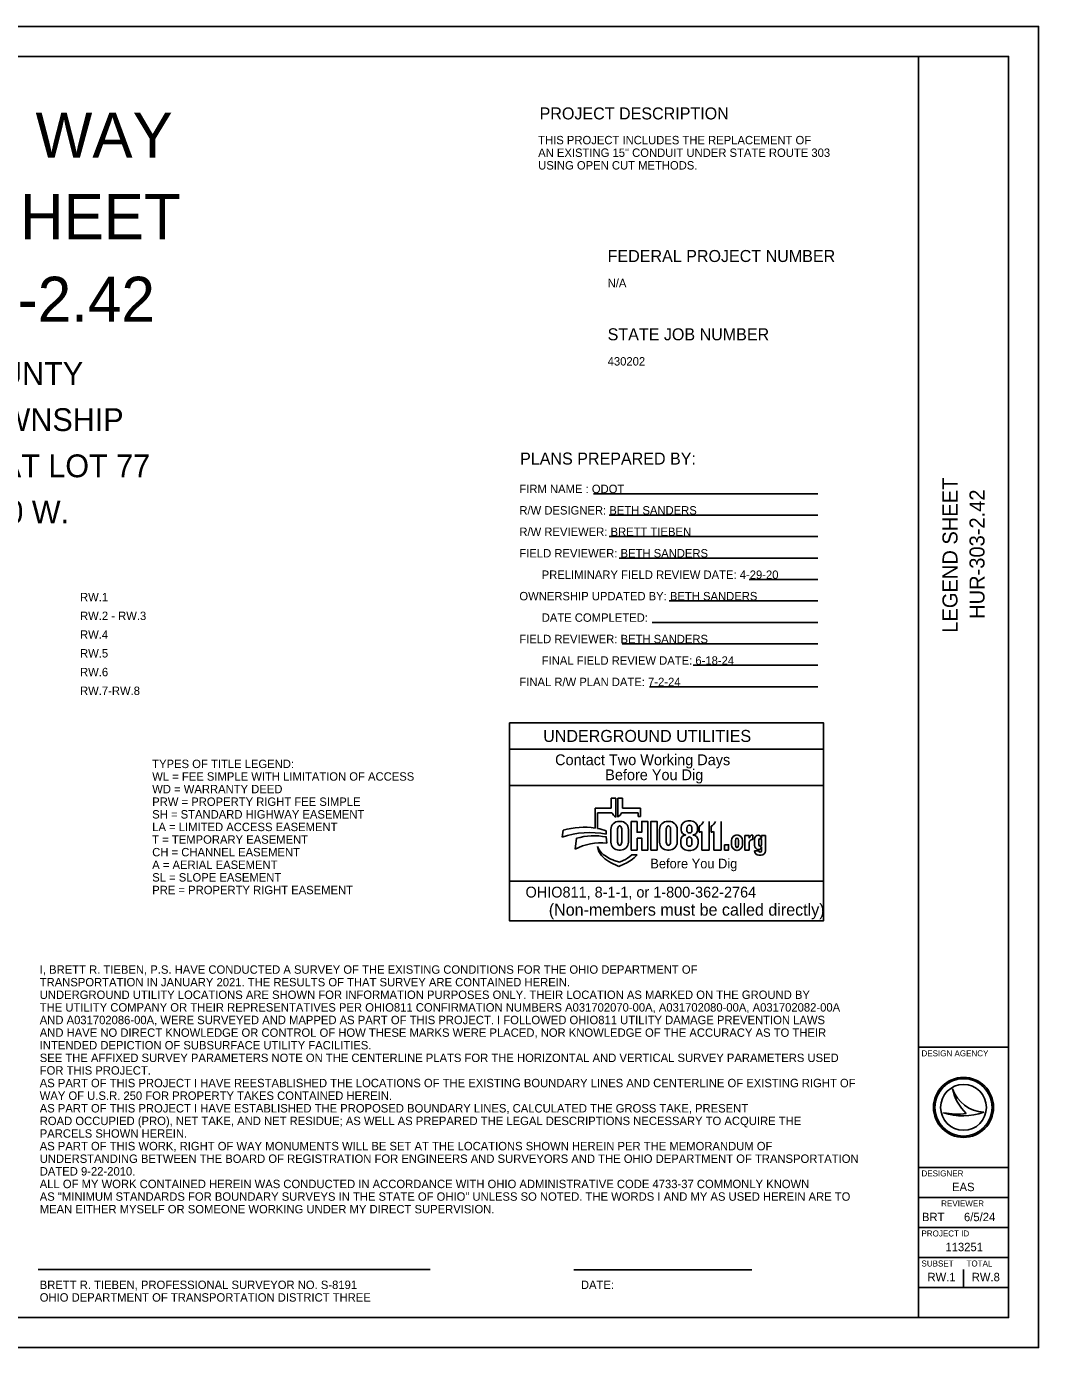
# Model space of a CAD drawing. Extents: x 0 to 34, y 0 to 22.
# Drawn here: x 17.15 to 34, y 0 to 22 of the extents above; entities that cross this region are included whole.
import ezdxf

# ---------------------------------------------------------------- set-up
doc = ezdxf.new("R2010")
doc.units = 0
for name, color, linetype in [('Default', 7, 'Continuous'), ('SH_Border', 7, 'Continuous'), ('SH_Cut_Line', 7, 'Continuous'), ('SH_Data', 7, 'Continuous'), ('SH_Text', 7, 'Continuous')]:
    doc.layers.add(name, color=color, linetype=linetype)

msp = doc.modelspace()

# ---------------------------------------------------------------- linework, layer by layer
at = {"layer": 'Default'}
for p, q in [((17.342, 1.298), (23.871, 1.298)), ((26.261, 1.297), (29.226, 1.297))]:
    msp.add_line(p, q, dxfattribs=at)
at = {"layer": 'SH_Border'}
for p, q in [((32, 0.5), (32, 21.5)), ((32, 5), (33.5, 5)), ((32, 3), (33.5, 3)), ((32, 2.5), (33.5, 2.5)), ((32, 2), (33.5, 2)), ((32, 1.5), (33.5, 1.5)), ((32, 1), (33.5, 1))]:
    msp.add_line(p, q, dxfattribs=at)
msp.add_lwpolyline([(1.5, 21.5), (33.5, 21.5), (33.5, 0.5), (1.5, 0.5)], close=True, dxfattribs=at)
at = {"layer": 'SH_Cut_Line'}
msp.add_lwpolyline([(0, 0), (34, 0), (34, 22), (0, 22)], close=True, dxfattribs=at)
at = {"layer": 'SH_Data'}
for p, q in [((26.961, 9.151), (26.881, 9.151)), ((26.881, 9.151), (26.881, 8.984)), ((26.961, 8.834), (26.961, 9.151)), ((27.072, 9.151), (26.992, 9.151)), ((26.992, 9.151), (26.992, 8.834)), ((27.072, 8.984), (27.072, 9.151)), ((26.881, 8.984), (26.618, 8.984)), ((26.618, 8.984), (26.618, 8.65)), ((26.655, 8.643), (26.655, 8.907)), ((26.655, 8.907), (26.896, 8.907)), ((27.056, 8.907), (27.335, 8.907)), ((27.369, 8.984), (27.072, 8.984)), ((27.335, 8.907), (27.335, 8.844)), ((27.335, 8.844), (27.369, 8.844)), ((27.369, 8.844), (27.369, 8.984)), ((26.083, 8.615), (26.069, 8.499)), ((26.802, 8.548), (26.802, 8.606)), ((26.879, 8.629), (26.879, 8.417)), ((26.988, 8.434), (26.988, 8.617)), ((27.037, 8.763), (27.013, 8.763)), ((27.062, 8.617), (27.062, 8.434)), ((27.171, 8.417), (27.171, 8.629)), ((27.315, 8.761), (27.214, 8.761)), ((27.214, 8.761), (27.214, 8.283)), ((27.69, 8.629), (27.69, 8.417)), ((27.799, 8.434), (27.799, 8.617)), ((27.848, 8.763), (27.823, 8.763)), ((27.873, 8.617), (27.873, 8.434)), ((27.982, 8.417), (27.982, 8.629)), ((28.046, 8.655), (28.046, 8.619)), ((28.145, 8.602), (28.145, 8.661)), ((28.209, 8.769), (28.16, 8.769)), ((28.226, 8.661), (28.226, 8.602)), ((28.323, 8.619), (28.323, 8.655)), ((28.346, 8.581), (28.346, 8.683)), ((28.394, 8.283), (28.394, 8.595)), ((28.513, 8.761), (28.513, 8.283)), ((28.546, 8.581), (28.546, 8.683)), ((28.595, 8.283), (28.595, 8.595)), ((28.713, 8.761), (28.713, 8.283)), ((26.303, 8.48), (26.281, 8.301)), ((26.812, 8.397), (26.802, 8.503)), ((27.315, 8.283), (27.315, 8.485)), ((28.041, 8.449), (28.041, 8.398)), ((28.142, 8.389), (28.142, 8.45)), ((28.227, 8.45), (28.227, 8.389)), ((28.329, 8.398), (28.329, 8.449)), ((28.887, 8.374), (28.887, 8.442)), ((28.954, 8.373), (28.954, 8.442)), ((29.002, 8.442), (29.002, 8.373)), ((29.069, 8.442), (29.069, 8.374)), ((29.182, 8.527), (29.109, 8.527)), ((29.109, 8.527), (29.109, 8.283)), ((29.182, 8.48), (29.182, 8.527)), ((29.182, 8.283), (29.182, 8.411)), ((29.231, 8.46), (29.242, 8.46)), ((29.242, 8.535), (29.237, 8.535)), ((29.242, 8.46), (29.242, 8.535)), ((29.271, 8.362), (29.271, 8.466)), ((29.343, 8.376), (29.343, 8.452)), ((29.386, 8.482), (29.386, 8.528)), ((29.386, 8.528), (29.451, 8.528)), ((29.386, 8.452), (29.386, 8.376)), ((29.451, 8.528), (29.451, 8.27)), ((26.654, 8.343), (26.659, 8.317)), ((27.013, 8.283), (27.037, 8.283)), ((27.214, 8.283), (27.315, 8.283)), ((27.313, 8.203), (27.227, 8.203)), ((27.31, 8.201), (27.313, 8.203)), ((27.823, 8.283), (27.848, 8.283)), ((28.162, 8.277), (28.208, 8.277)), ((28.513, 8.283), (28.394, 8.283)), ((28.713, 8.283), (28.595, 8.283)), ((29.109, 8.283), (29.182, 8.283)), ((29.271, 8.27), (29.343, 8.27)), ((29.381, 8.2), (29.341, 8.2)), ((29.386, 8.27), (29.386, 8.339)), ((27.019, 8.083), (26.931, 8.113)), ((26.955, 8.037), (27.01, 8.012)), ((27.01, 8.012), (27.105, 8.053)), ((27.081, 8.109), (27.019, 8.083)), ((30.417, 7.105), (25.192, 7.105)), ((32.567, 4.31), (32.567, 4.31)), ((32.75, 4), (32.75, 4)), ((32.417, 3.91), (32.417, 3.91)), ((33.087, 3.919), (33.087, 3.919)), ((32.75, 1), (32.75, 1.3))]:
    msp.add_line(p, q, dxfattribs=at)
for points in [[(25.192, 10.405), (30.417, 10.405), (30.417, 9.965), (25.192, 9.965)], [(25.192, 9.965), (30.417, 9.965), (30.417, 9.36), (25.192, 9.36)], [(25.192, 9.36), (30.417, 9.36), (30.417, 7.765), (25.192, 7.765)], [(28.771, 8.373), (28.837, 8.373), (28.837, 8.283), (28.771, 8.283)], [(25.192, 7.765), (30.417, 7.765), (30.417, 7.105), (25.192, 7.105)]]:
    msp.add_lwpolyline(points, close=True, dxfattribs=at)
for points in [[(27.315, 8.485), (27.391, 8.485), (27.391, 8.283), (27.493, 8.283), (27.493, 8.761), (27.391, 8.761), (27.391, 8.581), (27.315, 8.581), (27.315, 8.761)], [(27.544, 8.283), (27.646, 8.283), (27.646, 8.761), (27.544, 8.761), (27.544, 8.283)], [(28.127, 8.535), (28.127, 8.535)], [(28.243, 8.535), (28.243, 8.535)]]:
    msp.add_lwpolyline(points, dxfattribs=at)
for radius in [0.5, 0.477, 0.477, 0.382]:
    msp.add_circle((32.75, 4), radius, dxfattribs=at)
for centre, radius, start, end in [((27.033, 8.962), 0.147, 201.9296, 240.7469), ((26.92, 8.962), 0.147, 299.2531, 338.0704), ((26.426, 7.441), 1.224, 81.0007, 106.3144), ((26.426, 7.441), 1.224, 72.1402, 79.2074), ((27.013, 8.629), 0.134, 90, 180), ((27.037, 8.629), 0.134, 0, 90), ((27.823, 8.629), 0.134, 90, 180), ((27.848, 8.629), 0.134, 0, 90), ((28.16, 8.655), 0.114, 90, 180), ((28.13, 8.619), 0.0837, 180, 268.1442), ((28.209, 8.655), 0.114, 0, 90), ((28.24, 8.619), 0.0837, 272.2058, 0), ((28.296, 8.805), 0.132, 292.5572, 340.7355), ((28.334, 8.713), 0.132, 275.1733, 297.0931), ((28.496, 8.805), 0.132, 292.5572, 340.7355), ((28.534, 8.713), 0.132, 275.1733, 297.0931), ((26.52, 7.245), 1.332, 77.8238, 109.8274), ((26.709, 7.453), 0.95, 83.8248, 116.8021), ((26.602, 7.428), 1.094, 79.44, 105.8467), ((27.013, 8.417), 0.134, 180, 270), ((27.037, 8.417), 0.134, 270, 0), ((27.823, 8.417), 0.134, 180, 270), ((27.848, 8.417), 0.134, 270, 0), ((28.127, 8.449), 0.0865, 90, 180), ((28.162, 8.398), 0.121, 180, 270), ((28.208, 8.398), 0.121, 270, 0), ((28.243, 8.449), 0.0865, 0, 90), ((28.982, 8.442), 0.0956, 92.5886, 180), ((28.982, 8.374), 0.0956, 180, 267.4114), ((28.974, 8.442), 0.0956, 0, 87.4114), ((28.974, 8.374), 0.0956, 272.5886, 0), ((29.237, 8.48), 0.0548, 90, 180), ((29.231, 8.411), 0.0493, 90, 180), ((29.339, 8.466), 0.0686, 92.6865, 180), ((29.34, 8.362), 0.0692, 180, 265.7132), ((29.333, 8.482), 0.0524, 0, 86.9262), ((26.934, 8.451), 0.3, 201.0457, 232.5314), ((26.87, 8.353), 0.214, 189.6817, 216.0884), ((27.07, 8.498), 0.461, 216.0884, 235.7167), ((27.222, 8.826), 0.773, 232.5314, 241.794), ((27.095, 8.589), 0.504, 241.794, 250.9821), ((26.866, 8.603), 0.538, 293.4582, 312.0712), ((26.866, 8.603), 0.599, 293.4582, 317.8286), ((29.341, 8.27), 0.0699, 180, 270), ((29.339, 8.339), 0.0467, 264.7825, 0), ((29.381, 8.27), 0.0699, 270, 0), ((27.318, 8.863), 0.903, 235.7167, 246.2325), ((33.116, 4.498), 0.58, 198.9257, 198.9319), ((33.347, 4.47), 0.796, 191.6379, 191.6421), ((33.116, 4.498), 0.58, 198.9319, 267.1657), ((33.347, 4.47), 0.796, 191.6421, 226.0947), ((32.739, 4.87), 1.013, 251.4576, 290.0832), ((32.648, 5.154), 1.266, 259.4964, 259.4995), ((32.739, 4.87), 1.013, 251.4527, 251.4576), ((32.648, 5.154), 1.266, 259.4995, 276.6672)]:
    msp.add_arc(centre, radius, start, end, dxfattribs=at)
for centre, major_axis, ratio, start_param, end_param in [((27.025, 8.617), (0, 0.0723), 0.514403, 4.712389, 7.853982), ((27.836, 8.617), (0, 0.0723), 0.514403, 4.712389, 7.853982), ((28.186, 8.661), (0.0404, 0), 0.969373, 0, 3.141593), ((28.186, 8.602), (0.0404, 0), 0.818453, 3.141593, 6.283185), ((27.025, 8.434), (0, 0.0723), 0.514403, 1.570796, 4.712389), ((27.836, 8.434), (0, 0.0723), 0.514403, 1.570796, 4.712389), ((28.184, 8.45), (0, 0.0535), 0.794529, 4.712389, 7.853982), ((28.184, 8.389), (0.0425, 0), 0.959837, 3.141593, 6.283185), ((28.978, 8.442), (0, 0.0434), 0.553236, 4.712389, 7.853982), ((28.978, 8.373), (0, 0.046), 0.522014, 1.570796, 4.712389), ((29.364, 8.452), (0, 0.0275), 0.777179, 4.712389, 7.853982), ((29.364, 8.376), (0, 0.0275), 0.777179, 1.570796, 4.712389), ((29.364, 8.27), (0.0214, 0), 0.959012, 3.141593, 6.283185)]:
    msp.add_ellipse(centre, major_axis=major_axis, ratio=ratio, start_param=start_param, end_param=end_param, dxfattribs=at)
at = {"layer": 'SH_Text'}
for p, q in [((26.586, 14.219), (30.323, 14.219)), ((26.85, 13.862), (30.323, 13.862)), ((26.85, 13.505), (30.323, 13.505)), ((27.014, 13.148), (30.323, 13.148)), ((29.178, 12.79), (30.323, 12.79)), ((27.85, 12.433), (30.323, 12.433)), ((27.565, 12.076), (30.323, 12.076)), ((27.068, 11.719), (30.323, 11.719)), ((28.249, 11.362), (30.323, 11.362)), ((27.52, 11.005), (30.323, 11.005))]:
    msp.add_line(p, q, dxfattribs=at)

# ---------------------------------------------------------------- texts
at = {"layer": 'Default'}
for s, p in [('I, BRETT R. TIEBEN, P.S. HAVE CONDUCTED A SURVEY OF THE EXISTING CONDITIONS FOR THE OHIO DEPARTMENT OF', (17.367, 6.225)), ('TRANSPORTATION IN JANUARY 2021. THE RESULTS OF THAT SURVEY ARE CONTAINED HEREIN.', (17.367, 6.015)), ('UNDERGROUND UTILITY LOCATIONS ARE SHOWN FOR INFORMATION PURPOSES ONLY. THEIR LOCATION AS MARKED ON THE GROUND BY ', (17.367, 5.805)), ('THE UTILITY COMPANY OR THEIR REPRESENTATIVES PER OHIO811 CONFIRMATION NUMBERS A031702070-00A, A031702080-00A, A031702082-00A', (17.367, 5.595)), ('AND A031702086-00A, WERE SURVEYED AND MAPPED AS PART OF THIS PROJECT. I FOLLOWED OHIO811 UTILITY DAMAGE PREVENTION LAWS', (17.367, 5.385)), ('AND HAVE NO DIRECT KNOWLEDGE OR CONTROL OF HOW THESE MARKS WERE PLACED, NOR KNOWLEDGE OF THE ACCURACY AS TO THEIR', (17.367, 5.175)), ('INTENDED DEPICTION OF SUBSURFACE UTILITY FACILITIES.', (17.367, 4.965)), ('SEE THE AFFIXED SURVEY PARAMETERS NOTE ON THE CENTERLINE PLATS FOR THE HORIZONTAL AND VERTICAL SURVEY PARAMETERS USED ', (17.367, 4.755)), ('FOR THIS PROJECT.', (17.367, 4.545)), ('AS PART OF THIS PROJECT I HAVE REESTABLISHED THE LOCATIONS OF THE EXISTING BOUNDARY LINES AND CENTERLINE OF EXISTING RIGHT OF ', (17.367, 4.335)), ('WAY OF U.S.R. 250 FOR PROPERTY TAKES CONTAINED HEREIN.', (17.367, 4.125)), ('AS PART OF THIS PROJECT I HAVE ESTABLISHED THE PROPOSED BOUNDARY LINES, CALCULATED THE GROSS TAKE, PRESENT', (17.367, 3.915)), ('ROAD OCCUPIED (PRO), NET TAKE, AND NET RESIDUE; AS WELL AS PREPARED THE LEGAL DESCRIPTIONS NECESSARY TO ACQUIRE THE', (17.367, 3.705)), ('PARCELS SHOWN HEREIN.', (17.367, 3.495)), ('AS PART OF THIS WORK, RIGHT OF WAY MONUMENTS WILL BE SET AT THE LOCATIONS SHOWN HEREIN PER THE MEMORANDUM OF ', (17.367, 3.285)), ('UNDERSTANDING BETWEEN THE BOARD OF REGISTRATION FOR ENGINEERS AND SURVEYORS AND THE OHIO DEPARTMENT OF TRANSPORTATION ', (17.367, 3.075)), ('DATED 9-22-2010.', (17.367, 2.865)), ('ALL OF MY WORK CONTAINED HEREIN WAS CONDUCTED IN ACCORDANCE WITH OHIO ADMINISTRATIVE CODE 4733-37 COMMONLY KNOWN', (17.367, 2.655)), ('AS "MINIMUM STANDARDS FOR BOUNDARY SURVEYS IN THE STATE OF OHIO" UNLESS SO NOTED. THE WORDS I AND MY AS USED HEREIN ARE TO', (17.367, 2.445)), ('MEAN EITHER MYSELF OR SOMEONE WORKING UNDER MY DIRECT SUPERVISION.', (17.367, 2.235)), ('BRETT R. TIEBEN, PROFESSIONAL SURVEYOR NO. S-8191                                                               ', (17.367, 0.975)), (' DATE:', (26.327, 0.975)), ('OHIO DEPARTMENT OF TRANSPORTATION DISTRICT THREE', (17.367, 0.765))]:
    msp.add_text(s, height=0.14, dxfattribs=at).set_placement(p)
at = {"layer": 'SH_Data'}
for s, height, p in [('RIGHT OF WAY', 0.75, (12.227, 19.816)), ('LEGEND SHEET', 0.75, (11.968, 18.457)), (' HUR-303-2.42', 0.75, (12.541, 17.082)), ('      HURON COUNTY     ', 0.38, (13.093, 16.03)), ('    WAKEMAN TOWNSHIP   ', 0.38, (12.694, 15.262)), ('SECTION 1, GREAT LOT 77', 0.38, (12.654, 14.493)), ('   T. 4 N., R. 20 W.   ', 0.38, (13.649, 13.725)), ('RW.1  ', 0.14, (18.038, 12.427)), ('RW.2 - RW.3 ', 0.14, (18.038, 12.115)), ('RW.4  ', 0.14, (18.038, 11.803)), ('RW.5  ', 0.14, (18.038, 11.491)), ('RW.6  ', 0.14, (18.038, 11.179)), ('RW.7-RW.8 ', 0.14, (18.038, 10.867)), ('UNDERGROUND UTILITIES', 0.2, (25.751, 10.085)), ('Contact Two Working Days', 0.18, (25.949, 9.698)), ('Before You Dig', 0.18, (26.784, 9.448)), ('Before You Dig', 0.15972, (27.535, 7.98)), ('OHIO811, 8-1-1, or 1-800-362-2764', 0.18, (25.457, 7.494)), ('(Non-members must be called directly)', 0.2, (25.844, 7.192)), ('DESIGN AGENCY', 0.1, (32.05, 4.85)), ('DESIGNER', 0.1, (32.05, 2.85)), ('EAS', 0.14, (32.559, 2.605)), ('REVIEWER', 0.1, (32.378, 2.35)), ('BRT', 0.14, (32.058, 2.105)), ('6/5/24', 0.14, (32.758, 2.105)), ('PROJECT ID', 0.1, (32.05, 1.85)), ('113251', 0.14, (32.449, 1.605)), ('SUBSET', 0.1, (32.05, 1.35)), ('TOTAL', 0.1, (32.8, 1.35)), ('RW.1', 0.14, (32.15, 1.105)), ('RW.8', 0.14, (32.887, 1.105))]:
    msp.add_text(s, height=height, dxfattribs=at).set_placement(p)
for s, p in [('LEGEND SHEET', (32.65, 11.904)), ('HUR-303-2.42', (33.1, 12.134))]:
    msp.add_text(s, height=0.25, rotation=90, dxfattribs=at).set_placement(p)
at = {"layer": 'SH_Text'}
for s, height, p in [('PROJECT DESCRIPTION', 0.2, (25.691, 20.451)), ('THIS PROJECT INCLUDES THE REPLACEMENT OF', 0.14, (25.667, 20.037)), ('AN EXISTING 15" CONDUIT UNDER STATE ROUTE 303', 0.14, (25.667, 19.827)), ('USING OPEN CUT METHODS.', 0.14, (25.667, 19.617)), ('FEDERAL PROJECT NUMBER', 0.2, (26.824, 18.077)), ('N/A       ', 0.14, (26.824, 17.657)), ('STATE JOB NUMBER', 0.2, (26.824, 16.773)), ('430202    ', 0.14, (26.824, 16.353)), ('PLANS PREPARED BY:', 0.2, (25.366, 14.704)), ('FIRM NAME : ODOT', 0.14, (25.354, 14.229)), ('R/W DESIGNER: BETH SANDERS', 0.14, (25.354, 13.872)), ('R/W REVIEWER: BRETT TIEBEN', 0.14, (25.354, 13.515)), ('FIELD REVIEWER: BETH SANDERS', 0.14, (25.354, 13.157)), ('PRELIMINARY FIELD REVIEW DATE: 4-29-20', 0.14, (25.726, 12.8)), ('OWNERSHIP UPDATED BY: BETH SANDERS', 0.14, (25.354, 12.443)), ('DATE COMPLETED:', 0.14, (25.726, 12.086)), ('FIELD REVIEWER: BETH SANDERS', 0.14, (25.354, 11.729)), ('FINAL FIELD REVIEW DATE: 6-18-24', 0.14, (25.726, 11.371)), ('FINAL R/W PLAN DATE: 7-2-24', 0.14, (25.354, 11.015)), ('TYPES OF TITLE LEGEND:', 0.14, (19.24, 9.65)), ('WL = FEE SIMPLE WITH LIMITATION OF ACCESS', 0.14, (19.24, 9.44)), ('WD = WARRANTY DEED', 0.14, (19.24, 9.23)), ('PRW = PROPERTY RIGHT FEE SIMPLE', 0.14, (19.24, 9.02)), ('SH = STANDARD HIGHWAY EASEMENT', 0.14, (19.24, 8.81)), ('LA = LIMITED ACCESS EASEMENT', 0.14, (19.24, 8.6)), ('T = TEMPORARY EASEMENT', 0.14, (19.24, 8.39)), ('CH = CHANNEL EASEMENT', 0.14, (19.24, 8.18)), ('A = AERIAL EASEMENT', 0.14, (19.24, 7.97)), ('SL = SLOPE EASEMENT', 0.14, (19.24, 7.76)), ('PRE = PROPERTY RIGHT EASEMENT', 0.14, (19.24, 7.55))]:
    msp.add_text(s, height=height, dxfattribs=at).set_placement(p)

doc.saveas('drawing.dxf')
